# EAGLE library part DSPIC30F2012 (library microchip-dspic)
dsPIC Sensor DSP
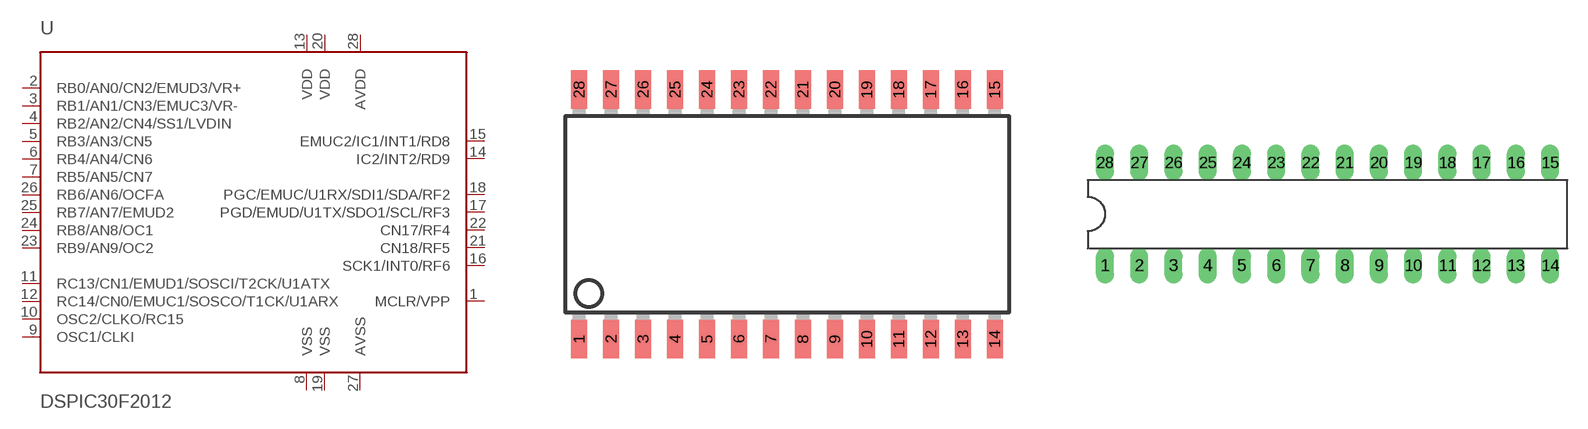
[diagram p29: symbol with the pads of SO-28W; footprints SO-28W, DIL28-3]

Designator prefix -

## DSPIC30F2012/SO  [SO-28W]
1  MCLR/VPP  in
2  RB0/AN0/CN2/EMUD3/VR+
3  RB1/AN1/CN3/EMUC3/VR-
4  RB2/AN2/CN4/SS1/LVDIN
5  RB3/AN3/CN5
6  RB4/AN4/CN6
7  RB5/AN5/CN7
8  VSS  pwr
9  OSC1/CLKI  in
10  OSC2/CLKO/RC15
11  RC13/CN1/EMUD1/SOSCI/T2CK/U1ATX
12  RC14/CN0/EMUC1/SOSCO/T1CK/U1ARX
13  VDD  pwr
14  IC2/INT2/RD9
15  EMUC2/IC1/INT1/RD8
16  SCK1/INT0/RF6
17  PGD/EMUD/U1TX/SDO1/SCL/RF3
18  PGC/EMUC/U1RX/SDI1/SDA/RF2
19  VSS  pwr
20  VDD  pwr
21  CN18/RF5
22  CN17/RF4
23  RB9/AN9/OC2
24  RB8/AN8/OC1
25  RB7/AN7/EMUD2
26  RB6/AN6/OCFA
27  AVSS  pwr
28  AVDD  pwr

## DSPIC30F2012/SP  [DIL28-3]
Pads as for SO-28W

## DSPIC30F2012/ML  [QFN-S28-6X6]
1  RB2/AN2/CN4/SS1/LVDIN
2  RB3/AN3/CN5
3  RB4/AN4/CN6
4  RB5/AN5/CN7
5  VSS  pwr
6  OSC1/CLKI  in
7  OSC2/CLKO/RC15
8  RC13/CN1/EMUD1/SOSCI/T2CK/U1ATX
9  RC14/CN0/EMUC1/SOSCO/T1CK/U1ARX
10  VDD  pwr
11  IC2/INT2/RD9
12  EMUC2/IC1/INT1/RD8
13  SCK1/INT0/RF6
14  PGD/EMUD/U1TX/SDO1/SCL/RF3
15  PGC/EMUC/U1RX/SDI1/SDA/RF2
16  VSS  pwr
17  VDD  pwr
18  CN18/RF5
19  CN17/RF4
20  RB9/AN9/OC2
21  RB8/AN8/OC1
22  RB7/AN7/EMUD2
23  RB6/AN6/OCFA
24  AVSS  pwr
25  AVDD  pwr
26  MCLR/VPP  in
27  RB0/AN0/CN2/EMUD3/VR+
28  RB1/AN1/CN3/EMUC3/VR-

## Footprint SO-28W (pad centres in mm)
Small Outline Wide Plastic Gull Wing 300-mil body, package type SO
smd 0.635 x 1.524: 1 -7.62,-4.953; 2 -6.35,-4.953; 3 -5.08,-4.953; 4 -3.81,-4.953; 5 -2.54,-4.953; 6 -1.27,-4.953; 7 0,-4.953; 8 1.27,-4.953; 9 2.54,-4.953; 10 3.81,-4.953; 11 5.08,-4.953; 12 6.35,-4.953; 13 7.62,-4.953; 14 8.89,-4.953; 15 8.89,4.953; 16 7.62,4.953; 17 6.35,4.953; 18 5.08,4.953; 19 3.81,4.953; 20 2.54,4.953; 21 1.27,4.953; 22 0,4.953; 23 -1.27,4.953; 24 -2.54,4.953; 25 -3.81,4.953; 26 -5.08,4.953; 27 -6.35,4.953; 28 -7.62,4.953

## Footprint DIL28-3 (pad centres in mm)
Dual In Line package type P
drill 0.813 long: 1 -16.51,-3.81; 2 -13.97,-3.81; 3 -11.43,-3.81; 4 -8.89,-3.81; 5 -6.35,-3.81; 6 -3.81,-3.81; 7 -1.27,-3.81; 8 1.27,-3.81; 9 3.81,-3.81; 10 6.35,-3.81; 11 8.89,-3.81; 12 11.43,-3.81; 13 13.97,-3.81; 14 16.51,-3.81; 15 16.51,3.81; 16 13.97,3.81; 17 11.43,3.81; 18 8.89,3.81; 19 6.35,3.81; 20 3.81,3.81; 21 1.27,3.81; 22 -1.27,3.81; 23 -3.81,3.81; 24 -6.35,3.81; 25 -8.89,3.81; 26 -11.43,3.81; 27 -13.97,3.81; 28 -16.51,3.81

## Footprint QFN-S28-6X6 (pad centres in mm)
Quad Flat No Lead
smd 0.6 x 0.4: 1 2.75,-1.95; 2 2.75,-1.3; 3 2.75,-0.65; 4 2.75,0; 5 2.75,0.65; 6 2.75,1.3; 7 2.75,1.95; 15 -2.75,1.95; 16 -2.75,1.3; 17 -2.75,0.65; 18 -2.75,0; 19 -2.75,-0.65; 20 -2.75,-1.3; 21 -2.75,-1.95
smd 0.4 x 0.6: 8 1.95,2.75; 9 1.3,2.75; 10 0.65,2.75; 11 0,2.75; 12 -0.65,2.75; 13 -1.3,2.75; 14 -1.95,2.75; 22 -1.95,-2.75; 23 -1.3,-2.75; 24 -0.65,-2.75; 25 0,-2.75; 26 0.65,-2.75; 27 1.3,-2.75; 28 1.95,-2.75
